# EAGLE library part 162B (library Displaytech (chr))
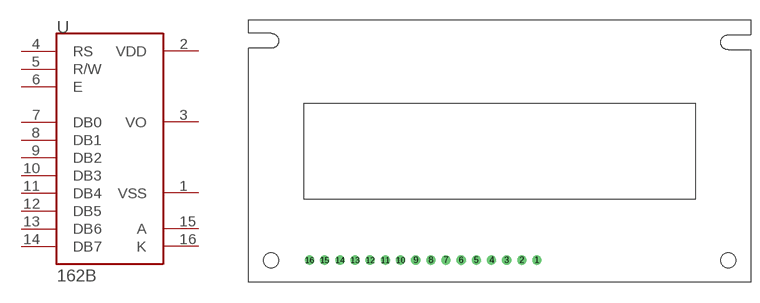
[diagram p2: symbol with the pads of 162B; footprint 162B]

Designator prefix -

## 162B  [162B]
1  VSS  pwr
2  VDD  pwr
3  VO  in
4  RS
5  R/W
6  E
7  DB0
8  DB1
9  DB2
10  DB3
11  DB4
12  DB5
13  DB6
14  DB7
15  A  pwr
16  K  pwr

## Footprint 162B (pad centres in mm)
drill 1.016 round: 1 38.1,0; 2 35.56,0; 3 33.02,0; 4 30.48,0; 5 27.94,0; 6 25.4,0; 7 22.86,0; 8 20.32,0; 9 17.78,0; 10 15.24,0; 11 12.7,0; 12 10.16,0; 13 7.62,0; 14 5.08,0; 15 2.54,0; 16 0,0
